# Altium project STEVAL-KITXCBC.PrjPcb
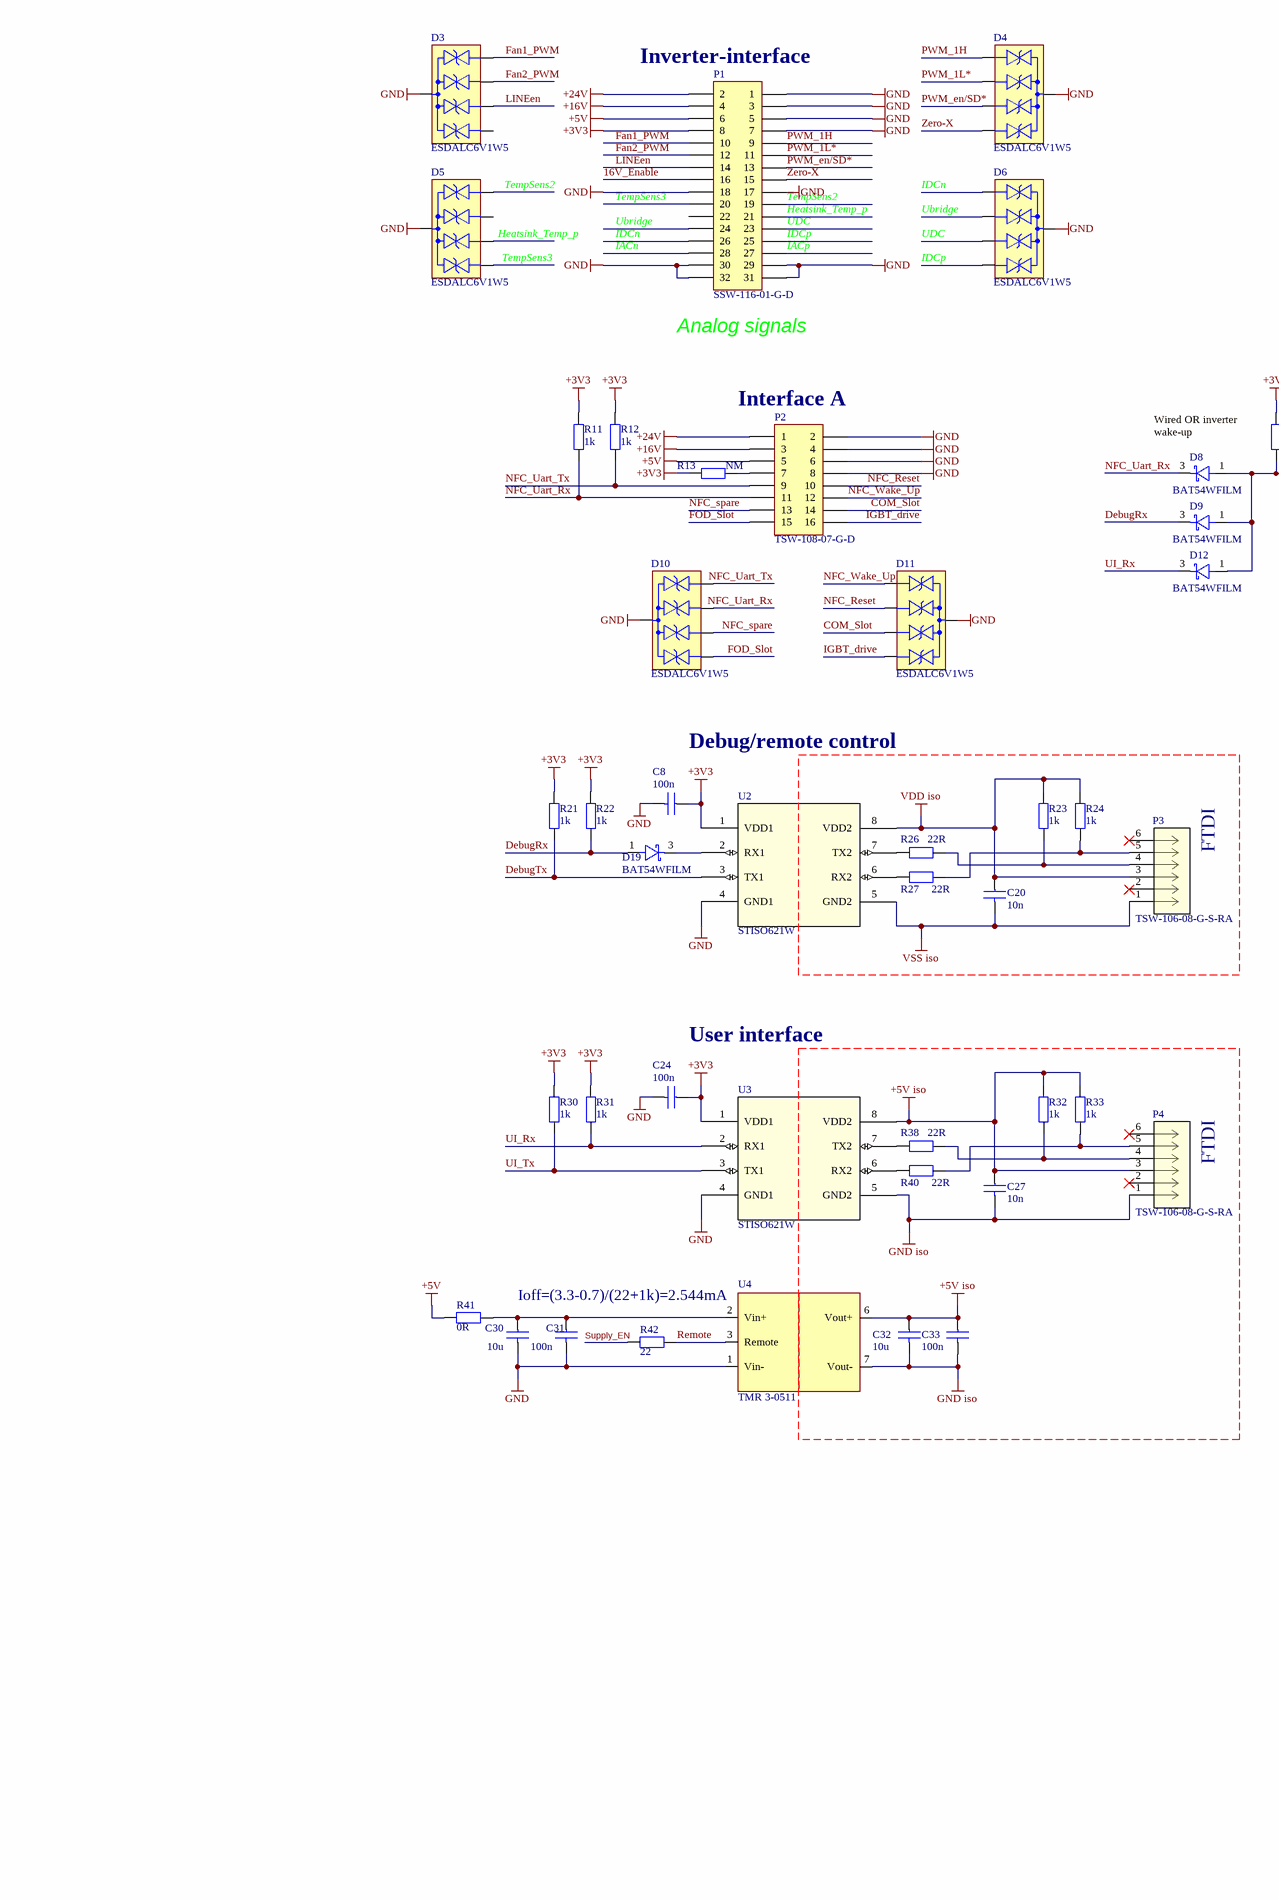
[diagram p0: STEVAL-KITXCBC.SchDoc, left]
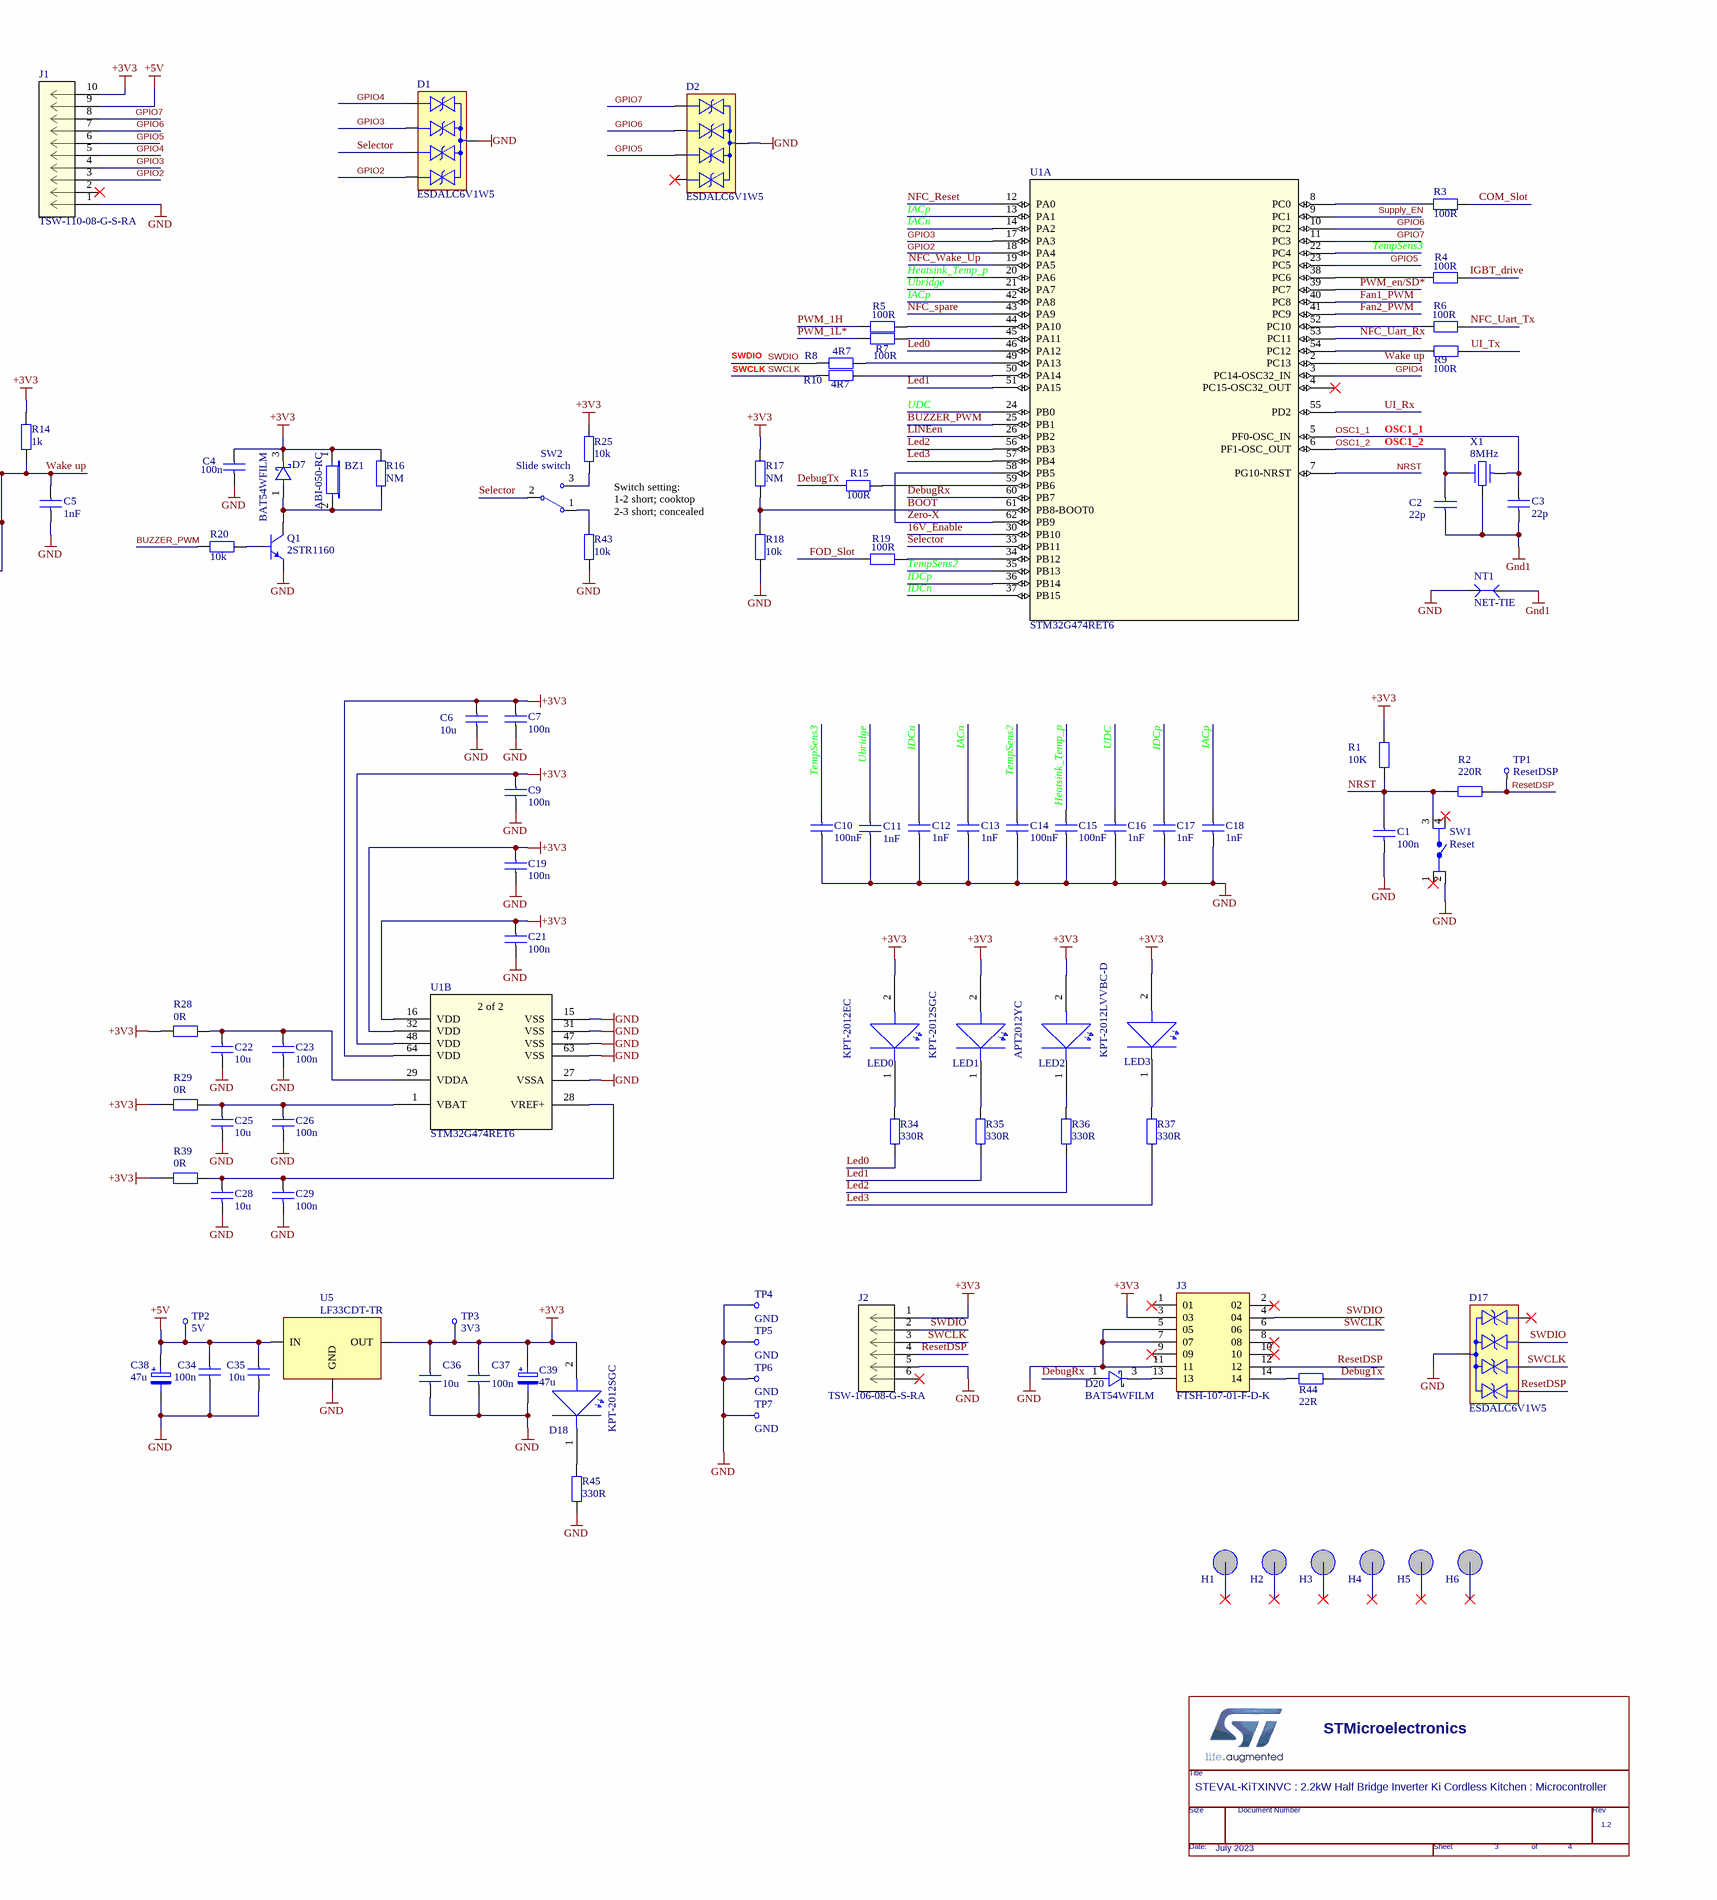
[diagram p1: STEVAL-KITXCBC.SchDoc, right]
1 sheet, 136 parts. Net scope: global (net labels, ports and power ports of the same name join across sheets).
Board file: STEVAL-KITXCBC.PcbDoc

## Sheet STEVAL-KITXCBC.SchDoc
size A2; SheetNumber: 3; SheetTotal: 4

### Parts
*?  Page Create Date: July 2023  RevCode: 1.2  Title: STEVAL-KiTXINVC : 2.2kW Half Bridge Inverter Ki Cordless Kitchen : Microcontroller  Page Number: 3  Page Count: 4  (hidden comment: ST_Standard_TitleBlock)  (graphical)
BZ1  ABI-050-RC  [TR_MP-ABI-050-RC_MTC]
C1  100n  [CC0805]
C2  22p  [CC0805]
C3  22p  [CC0805]
C4  100n  [CC0805]
C5  1nF  [CC0603]
C6  10u  [CC0805]
C7  100n  [CC0805]
C8  100n  [CC0805]
C9  100n  [CC0805]
C10  100nF  [CC0805]
C11  1nF  [CC0603]
C12  1nF  [CC0603]
C13  1nF  [CC0603]
C14  100nF  [CC0805]
C15  100nF  [CC0805]
C16  1nF  [CC0603]
C17  1nF  [CC0603]
C18  1nF  [CC0603]
C19  100n  [CC0805]
C20  10n  [CC0805]
C21  100n  [CC0805]
C22  10u  [CC0805]
C23  100n  [CC0805]
C24  100n  [CC0805]
C25  10u  [CC0805]
C26  100n  [CC0805]
C27  10n  [CC0805]
C28  10u  [CC0805]
C29  100n  [CC0805]
C30  10u  [CC0805]
C31  100n  [CC0805]
C32  10u  [CC0805]
C33  100n  [CC0805]
C34  100n  [CC0805]
C35  10u  [CC0805]
C36  10u  [CC0805]
C37  100n  [CC0805]
C38  47u  [ELCAP SMD D5H5.8P1.5]
C39  47u  [ELCAP SMD D5H5.8P1.5]
D1  ESDALC6V1W5  [SOT323_5]
D2  ESDALC6V1W5  [SOT323_5]
D3  ESDALC6V1W5  [SOT323_5]
D4  ESDALC6V1W5  [SOT323_5]
D5  ESDALC6V1W5  [SOT323_5]
D6  ESDALC6V1W5  [SOT323_5]
D7  BAT54WFILM  [SOT323]
D8  BAT54WFILM  [SOT323]
D9  BAT54WFILM  [SOT323]
D10  ESDALC6V1W5  [SOT323_5]
D11  ESDALC6V1W5  [SOT323_5]
D12  BAT54WFILM  [SOT323]
D17  ESDALC6V1W5  [SOT323_5]
D18  KPT-2012SGC  [LED_KPT-2012EC]
D19  BAT54WFILM  [SOT323]
D20  BAT54WFILM  [SOT323]
H1  Hole  [HOLE_M3 - D8]  (value not drawn)  (net tie, no BOM)
H2  Hole  [HOLE_M3 - D8]  (value not drawn)  (net tie, no BOM)
H3  Hole  [HOLE_M3 - D8]  (value not drawn)  (net tie, no BOM)
H4  Hole  [HOLE_M3 - D8]  (value not drawn)  (net tie, no BOM)
H5  Hole  [HOLE_M3 - D8]  (value not drawn)  (net tie, no BOM)
H6  Hole  [HOLE_M3 - D8]  (value not drawn)  (net tie, no BOM)
J1  TSW-110-08-G-S-RA  [SIP10 - Male - RA]
J2  TSW-106-08-G-S-RA  [SIP6 - Male - RA]
J3  FTSH-107-01-F-D-K  [SAMTEC-FTSH-107-01-X-D-K]
LED0  KPT-2012EC  [LED_KPT-2012EC]
LED1  KPT-2012SGC  [LED_KPT-2012EC]
LED2  APT2012YC  [LED_KPT-2012EC]
LED3  KPT-2012LVVBC-D  [LED_KPT-2012EC]
NT1  NET-TIE  [Net-Tie-0.3mm]  (net tie, no BOM)
P1  SSW-116-01-G-D  [HDR2X16]
P2  TSW-108-07-G-D  [HDR2X8]
P3  TSW-106-08-G-S-RA  [SIP6 - Male - RA]
P4  TSW-106-08-G-S-RA  [SIP6 - Male - RA]
Q1  2STR1160  [SOT23_3]
R1  10K  [RC0805]
R2  220R  [RC0805]
R3  100R  [RC0805]
R4  100R  [RC0805]
R5  100R  [RC0805]
R6  100R  [RC0805]
R7  100R  [RC0805]
R8  4R7  [RC0805]
R9  100R  [RC0805]
R10  4R7  [RC0805]
R11  1k  [RC0805]
R12  1k  [RC0805]
R13  NM  [RC0805]
R14  1k  [RC0805]
R15  100R  [RC0805]
R16  NM  [RC0805]
R17  NM  [RC0805]
R18  10k  [RC0805]
R19  100R  [RC0805]
R20  10k  [RC0805]
R21  1k  [RC0805]
R22  1k  [RC0805]
R23  1k  [RC0805]
R24  1k  [RC0805]
R25  10k  [RC0805]
R26  22R  [RC0805]
R27  22R  [RC0805]
R28  0R  [RC0805]
R29  0R  [RC0805]
R30  1k  [RC0805]
R31  1k  [RC0805]
R32  1k  [RC0805]
R33  1k  [RC0805]
R34  330R  [RC0805]
R35  330R  [RC0805]
R36  330R  [RC0805]
R37  330R  [RC0805]
R38  22R  [RC0805]
R39  0R  [RC0805]
R40  22R  [RC0805]
R41  0R  [RC0805]
R42  22  [RC0805]
R43  10k  [RC0805]
R44  22R  [RC0805]
R45  330R  [RC0805]
SW1  Reset  [PUSH  BUTTON SPST SIDE TH - LONG]
SW2  Slide switch  [Slide switch SPDT RA]
TP1  ResetDSP  [Terminal]
TP2  5V  [Terminal]
TP3  3V3  [Terminal]
TP4  GND  [Terminal]
TP5  GND  [Terminal]
TP6  GND  [Terminal]
TP7  GND  [Terminal]
U1  STM32G474RET6  [LQFP64-10x10mm]  (parts A,B of 2)
U2  STISO621W  [SO_SO621W_STM]
U3  STISO621W  [SO_SO621W_STM]
U4  TMR 3-0511  [VOLTAGE REGULATOR ISO SIP 8]
U5  LF33CDT-TR  [TO-252 DPAK]
X1  8MHz  [CRYSTAL_RESONATOR_SMD_5x3.2]

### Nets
+3V3: BZ1.1 C4.1 C6.1 C7.1 C8.1 C9.1 C19.1 C21.1 C24.1 C36.1 C37.1 C39.1(+) D7.3(Cathode) D18.2 J1.10 J2.1 J3.3(03) LED0.2 LED1.2 LED2.2 LED3.2 P1.8 R1.1 R11.2 R12.2 R13.1 R14.2 R16.2 R17.2 R21.2 R22.2 R25.2 R28.1 R29.1 R30.2 R31.2 R39.1 TP3.1(AmpIn) U1.16(VDD) U1.32(VDD) U1.48(VDD) U1.64(VDD) U2.1(VDD1) U3.1(VDD1) U5.3(OUT)
+5V: C34.1 C35.1 C38.1(+) J1.9 P1.6 P2.5 R41.2 TP2.1(AmpIn) U5.1(IN)
+5V iso: C27.1 C32.1 C33.1 P4.3 R32.2 R33.2 U3.8(VDD2) U4.6(Vout+)
+16V: P1.4 P2.3
+24V: P1.2 P2.1
GND: C1.2 C4.2 C5.2 C6.2 C7.2 C8.2 C9.2 C10.2 C11.2 C12.2 C13.2 C14.2 C15.2 C16.2 C17.2 C18.2 C19.2 C21.2 C22.2 C23.2 C24.2 C25.2 C26.2 C28.2 C29.2 C30.2 C31.2 C34.2 C35.2 C36.2 C37.2 C38.2(-) C39.2(-) D1.2(GND) D2.2(GND) D3.2(GND) D4.2(GND) D5.2(GND) D6.2(GND) D10.2(GND) D11.2(GND) D17.2(GND) J1.1 J2.5 J3.5(05) J3.7(07) J3.11 NT1.2 P1.1 P1.3 P1.5 P1.7 P1.17 P1.18 P1.29 P1.30 P1.31 P1.32 P2.2 P2.4 P2.6 P2.8 Q1.2(E) R18.2 R43.2 R45.2 SW1.2 TP4.1(AmpIn) TP5.1(AmpIn) TP6.1(AmpIn) TP7.1(AmpIn) U1.15(VSS) U1.27(VSSA) U1.31(VSS) U1.47(VSS) U1.63(VSS) U2.4(GND1) U3.4(GND1) U4.1(Vin-) U5.2(GND)
Gnd1: C2.1 C3.2 NT1.1 X1.2
GND iso: C27.2 C32.2 C33.2 P4.1 U3.5(GND2) U4.7(Vout-)
VDD iso: C20.1 P3.3 R23.2 R24.2 U2.8(VDD2)
VSS iso: C20.2 P3.1 U2.5(GND2)
16V_Enable: P1.16 U1.30(PB10)
BOOT: R17.1 R18.1 U1.61(PB8-BOOT0)
BUZZER_PWM: R20.2 U1.25(PB1)
COM_Slot: D11.4(I/O3) P2.14 R3.2
DebugRx: D9.3(Cathode) D19.1(Anode) D20.1(Anode) R22.1 U1.60(PB7)
DebugTx: R15.1 R21.1 R44.2 U2.3(TX1)
Fan1_PWM: D3.1(I/O1) P1.10 U1.40(PC8)
Fan2_PWM: D3.3(I/O2) P1.12 U1.41(PC9)
FOD_Slot: D10.5(I/O4) P2.15 R19.2
GPIO2: D1.5(I/O4) J1.3 U1.18(PA4)
GPIO3: D1.3(I/O2) J1.4 U1.17(PA3)
GPIO4: D1.1(I/O1) J1.5 U1.3(PC14-OSC32_IN)
GPIO5: D2.4(I/O3) J1.6 U1.23(PC5)
GPIO6: D2.3(I/O2) J1.7 U1.10(PC2)
GPIO7: D2.1(I/O1) J1.8 U1.11(PC3)
Heatsink_Temp_p: C15.1 D5.4(I/O3) P1.21 U1.20(PA6)
IACn: C13.1 P1.28 U1.14(PA2)
IACp: C18.1 P1.27 U1.13(PA1) U1.42(PA8)
IDCn: C12.1 D6.1(I/O1) P1.26 U1.37(PB15)
IDCp: C17.1 D6.5(I/O4) P1.25 U1.36(PB14)
IGBT_drive: D11.5(I/O4) P2.16 R4.2
Led0: R34.2 U1.46(PA12)
Led1: R35.2 U1.51(PA15)
Led2: R36.2 U1.56(PB3)
Led3: R37.2 U1.57(PB4)
LINEen: D3.4(I/O3) P1.14 U1.26(PB2)
NFC_Reset: D11.3(I/O2) P2.10 U1.12(PA0)
NFC_spare: D10.4(I/O3) P2.13 U1.43(PA9)
NFC_Uart_Rx: D8.3(Cathode) D10.3(I/O2) P2.11 R11.1 U1.53(PC11)
NFC_Uart_Tx: D10.1(I/O1) P2.9 R6.2 R12.1
NFC_Wake_Up: D11.1(I/O1) P2.12 U1.19(PA5)
NRST: C1.1 R1.2 R2.1 SW1.3 U1.7(PG10-NRST)
OSC1_1: C3.1 U1.5(PF0-OSC_IN) X1.3
OSC1_2: C2.2 U1.6(PF1-OSC_OUT) X1.1
PWM_1H: D4.1(I/O1) P1.9 R5.2
PWM_1L*: D4.3(I/O2) P1.11 R7.2
PWM_en/SD*: D4.4(I/O3) P1.13 U1.39(PC7)
Remote: R42.1 U4.3(Remote)
ResetDSP: D17.5(I/O4) J2.4 J3.12 R2.2 TP1.1(AmpIn)
Selector: D1.4(I/O3) SW2.2 U1.33(PB11)
Supply_EN: R42.2 U1.9(PC1)
SWCLK: D17.4(I/O3) J2.3 J3.6(06) R10.1
SWDIO: D17.3(I/O2) J2.2 J3.4(04) R8.1
TempSens2: C14.1 D5.1(I/O1) P1.19 U1.35(PB13)
TempSens3: C10.1 D5.5(I/O4) P1.20 U1.22(PC4)
Ubridge: C11.1 D6.3(I/O2) P1.24 U1.21(PA7)
UDC: C16.1 D6.4(I/O3) P1.23 U1.24(PB0)
UI_Rx: D12.3(Cathode) R31.1 U1.55(PD2) U3.2(RX1)
UI_Tx: R9.2 R30.1 U3.3(TX1)
Wake up: C5.1 D8.1(Anode) D9.1(Anode) D12.1(Anode) R14.1 U1.2(PC13)
Zero-X: D4.5(I/O4) P1.15 U1.58(PB5) U1.62(PB9)
NetBZ1_2: BZ1.2 D7.1(Anode) Q1.3(C) R16.1
NetC22_1: C22.1 C23.1 R28.2 U1.29(VDDA)
NetC25_1: C25.1 C26.1 R29.2 U1.1(VBAT)
NetC28_1: C28.1 C29.1 R39.2 U1.28(VREF+)
NetC30_1: C30.1 C31.1 R41.1 U4.2(Vin+)
NetD18_1: D18.1 R45.1
NetD19_3: D19.3(Cathode) U2.2(RX1)
NetD20_3: D20.3(Cathode) J3.13
NetJ3_14: J3.14 R44.1
NetLED0_1: LED0.1 R34.1
NetLED1_1: LED1.1 R35.1
NetLED2_1: LED2.1 R36.1
NetLED3_1: LED3.1 R37.1
NetP2_7: P2.7 R13.2
NetP3_4: P3.4 R23.1 R26.2
NetP3_5: P3.5 R24.1 R27.2
NetP4_4: P4.4 R32.1 R38.2
NetP4_5: P4.5 R33.1 R40.2
NetQ1_1: Q1.1(B) R20.1
NetR3_1: R3.1 U1.8(PC0)
NetR4_1: R4.1 U1.38(PC6)
NetR5_1: R5.1 U1.44(PA10)
NetR6_1: R6.1 U1.52(PC10)
NetR7_1: R7.1 U1.45(PA11)
NetR8_2: R8.2 U1.49(PA13)
NetR9_1: R9.1 U1.54(PC12)
NetR10_2: R10.2 U1.50(PA14)
NetR15_2: R15.2 U1.59(PB6)
NetR19_1: R19.1 U1.34(PB12)
NetR25_1: R25.1 SW2.3
NetR26_1: R26.1 U2.7(TX2)
NetR27_1: R27.1 U2.6(RX2)
NetR38_1: R38.1 U3.7(TX2)
NetR40_1: R40.1 U3.6(RX2)
NetR43_1: R43.1 SW2.1

Not connected (* = marked no-connect by the designer): D2 5(I/O4)*; D3 5(I/O4); D5 3(I/O2); D17 1(I/O1)*; H1 1*; H2 1*; H3 1*; H4 1*; H5 1*; H6 1*; J1 2*; J2 6*; J3 1(01)* 2(02)* 8(08)* 9(09)* 10*; P1 22; P3 2* 6*; P4 2* 6*; SW1 1* 4*; U1 4(PC15-OSC32_OUT)*

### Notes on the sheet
- (near P1) Inverter-interface
- (near P1) Analog signals
- (near P2) Interface A
- Wired OR inverter wake-up
- Switch setting:
  1-2 short; cooktop
  2-3 short; concealed
- Debug/remote control
- (near P3) FTDI
- User interface
- (near P4) FTDI
- (near U4) Ioff=(3.3-0.7)/(22+1k)=2.544mA
- Labels drawn without touching a wire or pin: SWDIO

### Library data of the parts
BZ1 = ABI-050-RC: Transducer, 2 V to 5 V, 75 dB, Sounder, 30 mA, Through Hole
C1 C4 C7-C9 C19-C21 C23 C24 C26 C27 C29 C32 C33 = CAP NP: Capacitor  0805; Manufacturer 1: VISHAY; MPN 1: VJ0805Y104KXACW1BC; Dielectric: X7R; SMT/THT: SMT; Voltage: 50V
C2 C3 = CAP NP: Capacitor  0805; Manufacturer 1: VISHAY; MPN 1: VJ0805A220JXBAC; Dielectric: NP0; SMT/THT: SMT
C5 C11 = CAP NP: Capacitor  0804; SMT/THT: SMT; Voltage: 50V
C6 C22 C25 C28 C30 C31 C34-C37 = CAP NP: Capacitor  0805; Manufacturer 1: MURATA; MPN 1: GCM21BR70J106KE22L; Dielectric: X7R; SMT/THT: SMT; Voltage: 6V3
C10 C14 C15 = CAP NP: Capacitor  0805; SMT/THT: SMT; Voltage: 50V
C12 C13 C16-C18 = CAP NP: Capacitor  0603; SMT/THT: SMT; Voltage: 50V
C38 C39 = Capacitor P_2: Cap Aluminum 47uF 16V 20% (5 X 5.8mm) SMD 0.36 Ohm 240mA 2000 hr 105°C Embossed T/R; Manufacturer 1: Panasonic; Manufacturer Part Number 1: EEE-FPC470UAR; Material: Aluminium; ESR (Equivalent Series Resistance): 360mR; Leakage Current: 7.5uA; Life (Hours): 2000Hour
D1-D6 D10 D11 D17 = Diode ESDALC6V1W5_1: Quad TRANSIL array for data protection TVS Diodes; Manufacturer 1: STMicroelectronics; Operating Supply Voltage: 3V; Direction: Unidirectional; Number of Elements: 4; Capacitance: 7.5pF; Reverse Breakdown Voltage: 6.1V; Element Configuration: Common Anode; Breakdown Voltage: 7.2V; Peak Pulse Power: 25W; Power Line Protection: No; Leakage Current: 1uA; Test Current: 1mA; ESD Protection: Yes; Peak Pulse Current: 15A; Diode Type: ZENER
D7-D9 D12 D19 D20 = Diode BAT54WFILM: Schottky Diode; Manufacturer 1: STMicroelectronics; Current Rating: 300mA; Forward Voltage: 900mV; Max Surge Current: 1A; Recovery Time: 5ns; Max Reverse Current: 1uA; Max Repetitive Reverse Voltage (Vrrm): 40V; Element Configuration: Single; Polarity: Standard; Voltage Rating (DC): 30V; Capacitance: 10pF
D18 LED1 = Component_1: LED KPT-2012SGC SMD (KINGBRIGHT) LED Low Power Green SMD 20 mA 2.2 V 568 nm
J1 = MC34755: No Description Available; Mfr_Name: Multicomp
J2 P3 P4 = 826947-6: No Description Available; Mfr_Name: TE Connectivity
J3 = FTSH-107-01-F-D-K: MF: Samtec Inc.
LED0 = Component_1: LED Uni-Color High Efficiency Red 625nm 2-Pin Chip LED T/R; Manufacturer 1: Kingbright
LED2 = Component_1: APT2012YC Yellow LED; 588 nm 2012 (0805) Clear; Rectangle Lens SMD package; Manufacturer 1: Kingbright
LED3 = Component_1: LED Single Chip Blue 470nm 30mA 2-Pin SMD T/R; Manufacturer 1: Kingbright; Forward Current: 2mA; Forward Voltage: 2.65V; Luminous Intensity: 24mcd; Viewing Angle: 140°; Lens Style: Rectangular
P1 = Header 16X2: Header, 16-Pin, Dual row; System: Connector
P2 = Header 8X2: Header, 8-Pin, Dual row
Q1 = NPN 2STR1160: NPN Bipolar Transistor; Manufacturer 1: STMicroelectronics; hFE Min: 180; Max Power Dissipation: 500mW; Number of Elements: 1; Collector Emitter Voltage (VCEO): 60V; Max Collector Current: 1A; Emitter Base Voltage (VEBO): 5V; Collector Emitter Saturation Voltage: 430mV; Element Configuration: Single
R1-R45 = RESISTOR: RESISTOR 0805; SMT/THT: SMT
SW1 = SWITCH TACT NO_2: Tact Switch Normally Open; MPN 1: SKHHNKA010; SMT/THT: SMT; Value: SKHHNKA010
SW2 = Slide Switch: Switch Slide ON None ON SPDT Side Slide 0.2A 30VDC 10000Cycle PC Pins Bracket Mount/Through Hole; Manufacturer 1: TE Connectivity AMP; Manufacturer Part Number 1: 1825232-1
TP1-TP7 = TESTP: Test Point; SMT/THT: THT
U1 = STM32G474RET6: MCU 32-Bit ARM Cortex-M4F RISC 512KB Flash 1.71V to 3.6V 64-Pin LQFP Tray; Mfr_Name: STMicroelectronics
U2 U3 = STISO621W: Digital Isolator, 2-Ch, -40 To 125Deg C Rohs Compliant: Yes ¦Stmicroelectronics STISO621WTR
U4 = Voltage regulator isolated 8P: DC/DC, Reg, 4.5-9Vin, 5Vo 0.6A, 3W, 1.5kV; Manufacturer 1: Traco Power
U5 = Voltage Regulator LDF33DT-TR: 3.3V 1A Very Low Drop Voltage Regulator; Manufacturer 1: STMicroelectronics; Number of Outputs: 1; Min Input Voltage: 2.6V; Max Input Voltage: 16V; Dropout Voltage: 200mV; Polarity: Positive; Quiescent Current: 800uA; Accuracy: 2%; Operating Supply Current: 200uA; Power Supply Rejection Ratio (PSRR): 60dB; Output Type: Fixed
X1 = Crystal Resonator 3P: Crystal, 8Mhz, 18Pf, 5Mm X 3.2Mm Frequency Nom 8Mhz Crystal Case Smd Rohs Compliant: Yes; Manufacturer 1: MULTICOMP PRO; Manufacturer Part Number 1: MCSJK-7I-8.00-18-30-60-B-30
